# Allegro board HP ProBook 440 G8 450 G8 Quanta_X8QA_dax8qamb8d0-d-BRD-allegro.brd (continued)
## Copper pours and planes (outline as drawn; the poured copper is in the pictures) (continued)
FBVDDQ_MEM on BOTTOM (solid shape): 43.55,67.37 43.63,67.34 43.66,67.28 43.73,67.11 43.88,67.03 43.9,67.02 44.04,66.88 44.04,66.86 44.15,66.66 44.36,66.58 44.43,66.55 44.44,66.44 44.4,66.43 44.37,66.43 44.13,66.33 44.03,66.1 44.04,66.09 44.01,66.01 43.94,65.98 43.74,65.9 43.66,65.7 43.72,65.53 43.87,65.43 43.88,65.43 44.04,65.27 44.04,65.25 44.15,65.05 44.36,64.97 44.43,64.94 44.46,64.88 44.46,64.86 44.44,64.81 44.39,64.8 44.33,64.82 44.26,64.83 44.11,64.79 44,64.69 43.91,64.65 43.83,64.7 43.71,64.81 43.55,64.85 43.53,64.84 43.45,64.87 43.42,64.93 43.33,65.11 43.14,65.18 43.12,65.18 43.08,65.2 43.07,65.24 43.07,65.27 43.24,65.44 43.25,65.44 43.37,65.54 43.42,65.7 43.35,65.88 43.18,65.98 43.12,66.01 43.1,66.08 43.1,66.12 43.12,66.19 43.18,66.22 43.42,66.5 43.18,66.78 43.12,66.81 43.1,66.88 43.1,66.92 43.12,66.99 43.18,67.02 43.35,67.12 43.42,67.3 43.42,67.33 43.43,67.34 43.46,67.37 43.48,67.37
FBVDDQ_MEM on BOTTOM (solid shape): outline of 417 points within 31.44,88.77 53.77,99.62
FBVDDQ_MEM on BOTTOM (solid shape): outline of 4834 points within 31.57,59.64 49.17,88.01
FBVDDQ_MEM on IN1 (solid shape): outline of 1805 points within 31.39,63.85 46.35,76.87
FBVDDQ_MEM on IN1 (solid shape): outline of 1967 points within 31.39,81.5 46.2,93.46
FBVDDQ_MEM on IN3 (solid shape): outline of 1001 points within 33.68,64.23 37.18,76.83
FBVDDQ_MEM on IN3 (solid shape): outline of 1517 points within 36.8,70.25 52.44,85.14
GPU_BST1 on BOTTOM (solid shape): 78.59,107.34 78.51,107.26 78.51,105.51 78.23,105.23 77.87,105.23 77.75,105.36 77.75,107.54 77.76,107.56 78.59,107.56
GPU_BST2 on BOTTOM (solid shape): 56.87,105.41 56.87,104.72 56.79,104.65 56.75,104.6 56.11,103.96 56.11,103.3 56.06,103.25 55.47,103.25 55.42,103.3 55.42,104.06 56.21,104.85 56.21,105.38 56.31,105.48 56.79,105.48
GPU_PWM2 on BOTTOM (solid shape): 52.27,106.07 52.27,105 53.19,104.09 53.19,103.27 53.16,103.25 52.55,103.25 52.45,103.35 52.45,103.51 52.46,103.55 52.46,103.58 52.35,103.84 52.09,103.95 52.03,103.94 51.79,104.19 51.79,106.09 51.86,106.17 52.17,106.17
GPU_SW1 on BOTTOM (solid shape): 76.81,108.4 76.81,106.86 76.55,106.6 76.12,106.6 75.92,106.4 75.92,105.13 76.2,104.85 78.36,104.85 78.53,104.67 78.53,102.49 78.18,102.13 73.91,102.13 73.66,102.39 73.66,104.72 74.01,105.08 74.01,106.14 74.24,106.37 74.24,108.48 76.73,108.48
GPU_SW2 on BOTTOM (solid shape): 63.32,105.33 63.32,102.41 63.19,102.28 62.02,102.28 59.51,99.77 54.58,99.77 54.53,99.82 54.53,102.21 54.58,102.26 57.63,102.26 58.06,102.69 58.06,104.19 57.91,104.34 57.9,104.36 57.77,104.56 57.55,104.63 57.45,104.62 57.35,104.57 57.32,104.55 57.22,104.65 57.22,105.31 57.31,105.4 63.26,105.4
ISL95860_VDD on BOTTOM (solid shape): 82.95,108.45 82.95,107.77 82.66,107.48 81.41,107.48 81.31,107.58 81.31,108.23 81.77,108.69 82.71,108.69
ISL95860_VIN on BOTTOM (solid shape): 83.92,111.2 83.92,110.36 83.83,110.27 82.91,110.27 82.72,110.08 82.72,110.02 82.7,109.94 82.69,109.88 82.7,109.82 82.72,109.76 82.72,109.69 83.06,109.35 83.06,109.01 82.9,108.86 82.22,108.86 82.04,109.04 82.04,109.24 82.14,109.34 82.14,109.4 82.15,109.41 82.24,109.5 82.24,109.84 82.07,110.01 81.8,110.01 81.71,110.1 81.71,110.92 81.96,111.17 82.57,111.17 82.73,111.33 83.79,111.33
L_SPK+ on TOP (solid shape): 136.01,101.12 136.01,100.62 136.22,100.42 136.35,100.42 136.6,100.17 136.6,99.95 136.47,99.82 135.62,99.82 135.46,99.98 135.46,101.11 135.53,101.18 135.95,101.18
L_SPK+ on TOP (solid shape): 196.01,43.3 196.01,42.81 195.9,42.61 195.87,42.39 195.87,42.35 195.48,41.96 195.48,41.19 195.43,41.14 195.29,41.14 195.23,41.19 195.23,42.19 195.24,42.2 195.35,42.27 195.42,42.38 195.48,42.43 195.48,42.56 195.48,43.17 195.48,43.28 195.46,43.31 195.48,43.35 195.54,43.42 195.89,43.42
L_SPK+ on BOTTOM (solid shape): 137.35,102.54 137.35,100.62 137.34,100.6 137.26,100.51 136.98,100.51 136.72,100.26 136.72,99.97 136.49,99.74 136.1,99.74 135.42,100.42 135.42,101.71 135.81,102.11 135.81,102.46 135.94,102.58 137.31,102.58
L_SPK+ on IN3 (solid shape): 136.73,100.85 136.73,100.06 136.55,99.89 135.96,99.89 135.48,100.37 135.48,100.9 135.94,101.36 136.22,101.36
L_SPK+ on IN3 (solid shape): 197,44.52 197,44.42 197.05,44.42 197.18,44.3 197.18,43.76 196.47,43.05 196.47,42.95 195.81,42.29 195.65,42.29 195.48,42.47 195.48,43.46 196.7,44.68 196.85,44.68
L_SPK- on TOP (solid shape): 138.71,101.14 138.71,100.01 138.55,99.85 137.68,99.85 137.54,99.99 137.54,100.34 138,100.8 138,101.09 138.12,101.22 138.63,101.22
L_SPK- on TOP (solid shape): 195.37,43.24 195.37,43.17 195.37,42.57 195.37,42.48 195.12,42.22 195.12,41.31 195.01,41.2 194.89,41.2 194.8,41.28 194.8,42.42 194.81,42.47 194.81,42.59 194.8,42.65 194.8,43.04 194.81,43.09 194.82,43.14 194.82,43.23 194.83,43.25 194.95,43.37 195.24,43.37
L_SPK- on BOTTOM (solid shape): 138.69,102.54 138.69,100.05 138.54,99.9 137.73,99.9 137.6,100.02 137.6,100.49 137.61,100.5 137.61,102.54 137.71,102.64 138.59,102.64
L_SPK- on IN3 (solid shape): 138.68,101.16 138.68,100.04 138.51,99.87 137.66,99.87 137.56,99.96 137.56,101.26 137.87,101.56 138.28,101.56
L_SPK- on IN3 (solid shape): 195.86,44.68 195.86,44.14 195.35,43.63 195.35,42.39 195.25,42.29 194.97,42.29 194.84,42.42 194.84,43.86 194.94,43.97 194.94,44.47 195.29,44.82 195.72,44.82
LCD_P on TOP (solid shape): outline of 170 points within 24.03,35.08 32.94,38.12
LCD_P on BOTTOM (solid shape): 33.63,35.06 33.63,33.47 33.07,32.92 32.04,32.92 31.75,33.21 31.75,35.53 31.82,35.61 33.08,35.61
MP2941_SW1 on BOTTOM (solid shape): 115.78,106.64 115.78,105.87 115.76,105.87 115.76,105.08 115.78,105.08 115.78,104.58 116.08,104.28 116.08,103.14 116.58,102.64 117.79,102.64 117.95,102.48 117.95,102.09 116.81,100.95 116.81,100.91 116.81,100.9 116.78,100.83 116.77,100.74 116.78,100.66 116.81,100.59 116.81,100.57 116.81,100.27 116.81,100.26 116.78,100.18 116.77,100.1 116.78,100.01 116.81,99.94 116.81,99.93 116.81,99.61 116.81,99.6 116.78,99.52 116.77,99.44 116.78,99.35 116.81,99.28 116.81,99.27 116.81,97.91 116.61,97.71 112.67,97.71 112.59,97.8 112.59,101.23 113.24,101.89 113.24,103.11 113.78,103.64 113.78,104.13 113.94,104.29 114.41,104.29 114.53,104.41 114.53,106.7 114.61,106.78 115.64,106.78
MP2941_VCC on BOTTOM (solid shape): 112.16,109.55 112.16,108.61 112.72,108.05 112.72,107.7 112.83,107.59 112.84,107.58 113.61,107.58 113.63,107.56 113.64,107.54 113.64,107.52 113.64,107.44 113.64,107.42 113.63,107.4 113.61,107.38 112.84,107.38 112.84,107.38 111.7,107.38 111.45,107.63 111.45,108.02 111,108.47 111,109.42 111.2,109.62 112.09,109.62
NB680ABST on BOTTOM (solid shape): 144.25,15.55 144.25,15.36 144.84,14.77 144.84,13.36 144.82,13.33 144.56,13.19 144.46,12.94 144.53,12.73 144.71,12.59 144.78,12.52 144.75,12.43 144.71,12.38 143.7,12.38 143.51,12.57 143.51,13.42 143.63,13.54 143.64,13.55 143.81,13.68 143.88,13.89 143.86,14.01 143.8,14.11 143.8,14.69 143.8,14.7 143.8,14.74 142.99,15.55 142.99,15.7 143.04,15.75 144.05,15.75
NB680ABST_S on BOTTOM (solid shape): 144.85,11.91 145.62,11.91 145.74,11.78 145.74,11.15 145.62,11.02 143.71,11.02 143.53,11.2 143.53,11.96 143.63,12.06 144.7,12.06
NB680ABSW on TOP (solid shape): 145.02,16.29 145.02,14.79 144.83,14.61 144.82,14.6 144.8,14.59 144,14.59 143.84,14.76 143.84,15.64 144.07,15.87 144.07,15.91 144.57,16.41 144.9,16.41
NB680ABSW on BOTTOM (solid shape): 148.61,16.76 148.61,13.1 147.55,12.04 146.24,12.04 146.19,12.05 146.15,12.05 146.11,12.05 146.06,12.04 145.51,12.04 145.29,12.26 145.29,14.87 144.21,15.94 144.21,15.94 144.15,16 142.25,16 142.17,16.08 142.17,16.28 142.27,16.37 144.36,16.37 144.99,17 148.37,17
NB691_BS on BOTTOM (solid shape): 124.1,14.93 124.1,14.27 124.36,14.02 124.89,14.02 124.99,13.92 124.99,13.31 124.92,13.23 123.59,13.23 123.24,13.59 123.24,14.96 123.11,15.09 122.76,15.09 122.68,15.16 122.68,15.44 123.44,15.44 123.44,15.47 123.57,15.47
NB691_BST on BOTTOM (solid shape): 125.96,12.88 125.96,12.06 125.8,11.91 124.2,11.91 124.1,12.01 124.1,12.95 124.18,13.03 125.8,13.03
NB691_LX on TOP (solid shape): 127.56,14.78 127.56,13.41 127.38,13.23 126.95,13.23 126.12,14.06 125.36,14.06 125.27,14.15 125.27,14.68 125.47,14.88 127.46,14.88
NB691_LX on BOTTOM (solid shape): 127.53,16.63 127.53,13.46 126.85,12.77 126.85,12.7 126.78,12.64 126.77,12.63 126.66,12.52 126.34,12.52 126.21,12.65 126.21,13.21 126.08,13.33 125.32,13.33 125.19,13.46 125.19,14.09 125.02,14.27 124.51,14.27 124.33,14.45 124.33,14.97 123.59,15.71 121.9,15.71 121.87,15.75 121.87,15.88 121.93,15.95 123.38,15.95 123.92,16.49 124.47,16.49 124.94,16.96 127.2,16.96
NPCE576H_AGND on BOTTOM (solid shape): 193.29,14.67 193.33,14.62 193.92,14.62 193.98,14.56 193.98,13.75 193.96,13.68 193.95,13.62 193.99,13.47 194.09,13.36 194.13,13.33 194.17,13.31 194.2,13.31 194.2,13.31 194.31,13.31 194.47,13.15 194.47,13.15 194.58,13.05 194.73,13.02 194.77,13.02 194.82,13.03 194.91,13.03 194.97,13.06 195.02,13.1 195.56,13.1 195.61,13.08 195.87,13.08 195.94,13.12 195.97,13.12 196.11,12.98 196.11,12.89 196.08,12.83 196.08,12.7 196.06,12.69 195.56,12.69 195.25,12.38 193.62,12.38 193.55,12.46 193.55,13.13 193.43,13.24 193.43,13.58 193.29,13.73 192.89,13.73 192.25,14.37 192.25,14.74 192.33,14.82 193.29,14.82
NVVDD on TOP (solid shape): outline of 938 points within 62.78,71.47 75.96,81.96
NVVDD on BOTTOM (solid shape): outline of 117 points within 59.51,94.18 77.75,101.28
NVVDD on BOTTOM (solid shape): outline of 2071 points within 62.93,72.25 79.32,83.34
NVVDD on IN1 (solid shape): outline of 2868 points within 61.59,72.25 80.91,102.61
NVVDD on SVCC (solid shape): 80.22,101.76 80.19,101.68 80.18,101.6 80.28,101.34 80.54,101.23 80.63,101.24 80.71,101.27 80.72,101.26 80.72,99.44 80.57,99.31 80.51,99.11 80.57,98.92 80.72,98.79 80.72,87.3 78.76,85.34 78.71,85.26 78.69,85.16 78.69,82.88 78.71,82.78 78.76,82.7 79.45,82.01 79.45,77.9 76.04,74.5 75,74.5 74.91,74.48 74.82,74.42 73.76,73.35 73.05,73.35 72.93,73.45 72.77,73.49 72.51,73.38 72.41,73.12 72.41,73.09 72.41,73.05 72.34,73.07 72.26,73.08 72,72.97 71.9,72.72 71.9,72.65 71.92,72.59 63.55,72.59 63.45,72.7 63.45,76.81 63.56,76.94 63.61,77.11 63.56,77.28 63.45,77.41 63.45,81.38 64.06,81.99 69.04,81.99 69.13,82.01 69.22,82.06 72.14,84.98 72.19,85.07 72.21,85.16 72.21,89.71 72.25,89.79 72.26,89.89 72.25,89.99 72.21,90.08 72.21,91.73 72.46,91.84 72.56,92.09 72.46,92.34 72.21,92.45 72.21,93.8 72.19,93.9 72.14,93.98 67.94,98.17 67.86,98.23 67.77,98.25 61.95,98.25 61.93,98.27 61.54,98.66 61.54,101.75 62.38,102.59 79.39,102.59
NVVDD on IN2 (solid shape): outline of 1516 points within 63.07,72.47 79.88,82.52
PEX_LX on BOTTOM (solid shape): 67.08,59.69 67.08,58.82 67.03,58.77 65.56,58.77 65.14,58.36 65.14,56.8 65.06,56.72 64.07,56.72 64.06,56.72 63.78,56.72 63.7,56.79 63.7,58.9 64.39,59.59 64.54,59.67 64.64,59.81 66.95,59.81
PEX_VDD on TOP (solid shape): 65.61,59.21 65.61,57.81 65.45,57.66 60.86,57.66 60.72,57.79 60.72,60.26 60.86,60.4 64.41,60.4
PEX_VDD on BOTTOM (solid shape): outline of 97 points within 53.52,57.43 61.44,71.75
PEX_VDD on IN1 (solid shape): outline of 1046 points within 55.98,57.1 67.1,72.49
PEX_VDD on IN2 (solid shape): 64.65,60.03 64.65,59.42 62.33,57.1 56.82,57.1 56.54,57.38 56.54,57.71 59.13,60.29 64.39,60.29
PEXVDD_EN1 on BOTTOM (solid shape): outline of 123 points within 82.09,83.26 85.29,85.9
PVADPTR on TOP (solid shape): 177.04,86.26 177.04,86.1 177.01,86.03 177,85.95 177.01,85.87 176.48,85.34 175.66,85.34 175.21,85.8 174.69,85.8 174.57,85.93 174.57,86.3 174.62,86.36 175.71,86.36 175.78,86.33 175.91,86 176.17,85.89 176.43,86 176.54,86.25 176.53,86.29 176.56,86.37 176.64,86.4 176.89,86.4
PVADPTR on BOTTOM (solid shape): outline of 145 points within 173.71,83.51 179.78,90.24
R_SPK+ on TOP (solid shape): 142.15,101.12 142.15,100.33 142.11,100.28 142.08,100.23 142.08,100.04 141.91,99.86 141.09,99.86 140.97,99.99 140.97,101.06 141.09,101.19 142.07,101.19
R_SPK+ on TOP (solid shape): 194.06,43.25 194.06,42.12 194.29,41.89 194.29,41.17 194.23,41.12 194.06,41.12 194.05,41.14 193.99,41.14 193.93,41.2 193.93,41.79 193.61,42.11 193.61,43.34 193.68,43.41 193.9,43.41
R_SPK+ on BOTTOM (solid shape): 142.03,102.42 142.03,100.1 141.85,99.92 141,99.92 140.87,100.05 140.87,100.42 140.78,100.51 140.41,100.51 140.35,100.57 140.35,102.56 140.43,102.64 141.81,102.64
R_SPK+ on IN3 (solid shape): 193.67,44.09 193.67,43.74 194.08,43.33 194.08,42.44 193.9,42.26 193.42,42.26 192.91,42.77 192.91,44.09 193.06,44.24 193.52,44.24
R_SPK+ on IN3 (solid shape): 142.31,100.65 142.31,100.41 142.14,100.3 142.07,100.1 142.1,99.97 142.17,99.87 142.09,99.78 141.09,99.78 140.92,99.96 140.92,100.65 141.45,101.18 141.78,101.18
R_SPK- on TOP (solid shape): 194.7,43.27 194.7,41.28 194.59,41.17 194.49,41.17 194.4,41.25 194.4,41.98 194.36,42.02 194.36,42.03 194.21,42.18 194.21,43.26 194.29,43.35 194.62,43.35
R_SPK- on TOP (solid shape): 140.06,101.06 140.06,100.65 140.1,100.61 140.1,100.19 140.1,100.15 140.1,100.11 140.1,100.08 140.1,99.99 139.99,99.87 139.08,99.87 139,99.95 139,101.04 139.13,101.17 139.96,101.17
R_SPK- on BOTTOM (solid shape): 140.08,102.47 140.08,100.02 139.96,99.9 139.1,99.9 138.94,100.05 138.94,102.44 139.14,102.64 139.91,102.64
R_SPK- on IN3 (solid shape): 140.08,101.05 140.08,99.91 139.98,99.81 139.75,99.81 139.69,99.87 139.33,99.87 139.25,99.95 139.13,99.95 138.99,100.1 138.99,100.98 139.16,101.16 139.98,101.16
R_SPK- on IN3 (solid shape): 194.69,44.8 194.69,43.89 194.71,43.86 194.71,42.47 194.56,42.31 194.33,42.31 194.21,42.44 194.21,43.56 193.93,43.84 193.93,44.83 194.03,44.93 194.56,44.93
SM_VREF on TOP (solid shape): 154.38,22.96 154.38,21.44 154,21.05 154,20.6 153.77,20.37 153.11,20.37 153.01,20.47 153.01,21.64 153.34,21.97 153.34,22.78 153.67,23.11 154.23,23.11
SMDDR_VREF_DQ1_M1 on TOP (solid shape): 111.73,24.66 111.73,24.23 111.94,24.03 113.05,24.03 113.18,23.9 113.18,23.16 112.98,22.96 112.22,22.96 111.99,22.73 111.99,20.85 111.76,20.62 110.87,20.62 110.81,20.69 110.81,21.98 111.05,22.22 111.05,23.92 110.89,24.08 110.89,24.69 110.97,24.76 111.63,24.76
SMDDR_VREF_DQ1_M3 on TOP (solid shape): 114.12,22.32 114.12,21.59 114.02,21.49 113.56,21.49 113.33,21.26 113.33,20.67 113.23,20.57 112.39,20.57 112.22,20.75 112.22,22.43 112.44,22.65 113.79,22.65
SN3V on TOP (solid shape): 145.86,15.63 145.86,13.5 145.69,13.33 145.14,13.33 145.01,13.46 145.01,13.83 145.13,13.95 145.13,15.62 145.21,15.69 145.79,15.69
SN_VCCIN2 on TOP (solid shape): 104.62,103.53 104.62,101.83 104.47,101.67 103.91,101.67 103.63,101.95 103.63,102.89 103.12,103.4 103.12,103.55 103.25,103.68 104.47,103.68
SY127F_LX on BOTTOM (solid shape): 170.43,17.42 170.43,17.24 171.32,16.36 172.34,16.36 172.46,16.23 172.46,12.88 172.29,12.7 170.48,12.7 170.13,13.05 170.13,13.38 169.85,13.66 165.4,13.66 165.3,13.76 165.3,14.17 165.45,14.32 169.95,14.32 170.13,14.5 170.13,16.46 169.72,16.86 169.72,17.42 169.85,17.55 169.9,17.55 170.01,17.65 170.2,17.65
TYPEC1_USB0 on BOTTOM (solid shape): 170.25,104.59 170.25,104.26 170.03,104.04 169.9,104.04 169.8,103.93 169.8,103.84 169.78,103.8 169.77,103.77 169.77,103.4 169.7,103.32 169.39,103.32 169.24,103.48 169.24,103.68 169.06,103.85 169.06,104.35 169.39,104.67 170.18,104.67
TYPEC1_USB0 on BOTTOM (solid shape): 181.27,88.51 181.97,88.51 182.31,88.17 182.31,87.89 182.3,87.87 182.3,87.35 182.8,86.84 182.83,86.84 183.11,86.56 183.61,86.56 183.82,86.36 183.82,84.8 183.73,84.72 182.63,84.72 182.45,84.53 181.56,84.53 181.25,84.22 180.45,84.22 180.37,84.31 180.31,84.47 180.19,84.59 180.19,86.76 180.58,87.16 180.58,88.5 180.67,88.59 181.18,88.59
TYPEC_VBUS on BOTTOM (solid shape): 204.58,103.57 204.58,101.82 204.57,101.82 204.57,101.19 204.29,100.91 202.31,100.91 202.16,101.06 202.16,103.03 202.5,103.86 202.68,104.04 203.1,104.21 203.93,104.21
TYPEC_VBUS on BOTTOM (solid shape): 211.75,107.65 211.81,107.65 211.83,107.62 211.92,107.62 211.96,107.6 212.16,107.6 212.29,107.47 212.29,107.26 212.16,107.13 210.82,107.13 210.36,106.68 209.9,106.68 209.83,106.75 209.83,107.03 210.13,107.34 210.13,107.57 210.34,107.77 210.44,107.77 210.54,107.87 211.52,107.87
TYPEC_VBUS on BOTTOM (solid shape): 189.91,89.05 189.91,87.95 189.84,87.88 189.71,87.88 189.71,88.89 189.51,88.89 189.51,87.88 189.31,87.88 189.31,88.89 189.11,88.89 189.11,87.88 188.8,87.88 188.64,87.73 188.64,87.45 188.58,87.39 187.61,87.39 187.56,87.44 187.56,87.45 187.49,87.56 187.38,87.63 187.12,87.63 187.1,87.63 186.95,87.63 186.84,87.55 186.77,87.45 186.77,87.3 186.71,87.25 186.71,84.83 186.61,84.73 185.93,84.73 185.82,84.63 185.47,84.63 185.21,84.38 184.86,84.38 184.41,84.83 184.41,88.37 184.11,88.67 184.11,88.96 184.38,89.23 185.72,89.23 185.93,89.43 189.53,89.43
TYPEC_VBUS on SVCC (solid shape): outline of 394 points within 180.67,87.32 196.29,105.17
TYPEC_VBUS on IN2 (solid shape): outline of 1202 points within 192.57,99.15 212.95,111.6
VADPBL on BOTTOM (solid shape): outline of 396 points within 147.21,84.55 174.88,100.28
N17777419 on BOTTOM (solid shape): 198.88,12.48 198.98,12.47 199.02,12.43 199.02,11.6 198.92,11.5 197.05,11.5 196.92,11.63 196.92,12.29 197.02,12.38 197.24,12.38 197.32,12.43 197.38,12.49 198.83,12.49
N25319276 on TOP (solid shape): 153.46,99.97 153.46,98.24 152.88,97.66 152.05,97.66 151.95,97.76 151.95,98.09 152.08,98.22 152.32,98.22 152.58,98.47 152.58,98.51 152.59,98.53 152.59,98.93 152.58,98.94 152.58,98.98 152.42,99.13 152.24,99.13 152.09,99.29 152.09,99.78 152.01,99.86 152.01,99.86 151.78,100.1 150.29,100.1 149.99,99.79 149.3,99.79 149.22,99.87 149.22,100.53 149.29,100.59 152.84,100.59
N27367629 on TOP (solid shape): 91,77.28 91.77,77.28 91.82,77.25 91.86,77.24 92.15,77.24 92.23,77.16 92.23,76.96 92.1,76.83 92.1,76.51 92,76.41 91.37,76.41 91.19,76.23 91.19,75.92 91.13,75.87 90.37,75.87 89.71,76.53 89.71,77.01 90.08,77.01 90.08,76.96 90.09,76.9 90.11,76.85 90.14,76.81 90.17,76.76 90.21,76.73 90.25,76.7 90.3,76.67 90.35,76.65 90.41,76.64 90.46,76.64 90.51,76.65 90.57,76.66 90.62,76.68 90.66,76.71 90.7,76.74 90.74,76.78 90.77,76.83 90.79,76.88 90.81,76.93 90.82,76.98 90.82,77.04 90.81,77.09 90.79,77.14 90.77,77.19 90.74,77.24 90.7,77.28 90.66,77.31 90.62,77.34 90.57,77.36 90.51,77.37 90.46,77.38 90.41,77.38 90.35,77.37 90.3,77.35 90.25,77.33 90.21,77.29 90.17,77.26 90.14,77.21 90.11,77.17 90.09,77.12 90.08,77.06 90.08,77.01 89.71,77.01 89.71,77.42 89.89,77.59 90.68,77.59
N27367663 on TOP (solid shape): 86.51,73.15 87.53,73.15 87.58,73.1 87.58,72.47 87.5,72.35 87.47,72.21 87.49,72.08 87.56,71.96 87.58,71.95 87.58,71.91 87.73,71.75 87.73,71.45 87.64,71.35 87.35,71.35 87.24,71.24 86.41,71.24 86.05,70.89 85.06,70.89 85.01,70.94 85.01,72.11 85.21,72.31 85.21,73.28 85.29,73.35 86.31,73.35
N27367840 on TOP (solid shape): 90.35,75.54 90.35,75.11 90.17,74.93 90.12,74.94 89.88,74.84 89.76,74.62 89.75,74.57 88.83,74.57 88.8,74.6 88.8,75.15 88.67,75.28 87.73,75.28 87.6,75.41 87.6,75.87 87.48,75.99 87.48,76.4 87.6,76.53 88.52,76.53 88.69,76.71 89.18,76.71
N27367840 on TOP (solid shape): 89.97,72.97 89.97,72.61 90.03,72.55 90.08,72.48 90.15,72.43 90.16,72.42 90.16,72.12 90.88,71.4 90.88,70.56 90.8,70.48 89.05,70.48 88.97,70.56 88.97,70.69 87.9,71.76 87.9,71.77 87.82,71.9 87.7,71.98 87.63,72.06 87.63,72.34 87.73,72.44 88.69,72.44 88.78,72.52 88.78,73.11 88.81,73.15 89.79,73.15
N27367840 on BOTTOM (solid shape): outline of 120 points within 86.79,71.33 89.69,77.04
N27367864 on TOP (solid shape): 86.38,77.75 86.38,77.45 86.52,77.31 86.59,77.28 86.6,77.28 86.69,77.19 87.12,77.19 87.32,76.99 87.32,75.92 87.45,75.79 87.45,75.31 87.53,75.22 87.53,74.61 87.5,74.57 86.62,74.57 86.22,74.97 86.24,75.04 86.24,75.08 86.13,75.34 85.88,75.44 85.77,75.43 85.68,75.39 85.64,75.36 85.61,75.4 85.41,75.4 85.11,75.69 85.11,77.25 85.12,77.29 85.12,77.93 85.32,78.13 86,78.13
N27368325 on BOTTOM (solid shape): 55.88,57.27 57.63,57.27 57.76,57.15 57.76,56.18 57.76,56.18 57.76,55.7 57.75,55.69 53.93,55.69 53.21,56.41 53.21,56.97 53.21,56.99 53.23,57.01 53.31,57.09 54.56,57.09 54.56,57.1 54.68,57.1 54.78,57 54.8,56.98 54.81,56.97 54.95,56.81 55.15,56.75 55.41,56.86 55.51,57.12 55.51,57.16 55.5,57.21 55.51,57.23 55.56,57.28 55.88,57.28
N36756780 on TOP (solid shape): 117.19,16.15 117.19,13.51 117.17,13.48 116.46,13.48 116.36,13.59 116.36,14.36 116.06,14.65 116.06,16.02 116.08,16.09 116.08,16.15 116.08,16.19 116.08,16.23 116.15,16.3 117.04,16.3
N37096732 on BOTTOM (solid shape): 174.62,85.98 174.62,84.96 173.07,83.41 172.13,83.41 172.08,83.46 172.08,84.02 172.13,84.07 172.13,84.66 172.18,84.71 173.02,84.71 173.91,85.6 173.91,85.98 173.99,86.05 174.55,86.05
N38936280 on TOP (solid shape): 66.06,12.37 66.06,10.56 65.94,10.44 63.02,10.44 62.74,10.72 62.74,13.74 63.24,14.25 64.18,14.25
N39257899 on TOP (solid shape): 196.57,42.34 196.57,42.19 195.96,41.58 195.93,41.58 195.83,41.48 195.83,41.2 195.78,41.15 195.63,41.15 195.58,41.2 195.58,41.88 195.91,42.22 195.98,42.27 196.04,42.34 196.19,42.49 196.42,42.49
N39257899 on TOP (solid shape): 193.42,43.91 193.42,42.11 193.81,41.72 193.81,41.46 193.7,41.35 192.81,41.35 191.79,42.36 191.79,43.36 191.76,43.39 191.76,43.76 191.77,43.81 191.77,43.85 191.77,43.89 191.76,43.98 191.82,44.04 193.29,44.04
N39257899 on BOTTOM (solid shape): 196.54,42.36 196.54,42.14 195.81,41.4 195.81,40.71 195.68,40.59 192.05,40.59 192.01,40.62 192.01,41.12 192.15,41.26 192.29,41.26 192.62,41.59 192.62,41.89 193.02,42.29 193.55,42.29 193.67,42.19 193.83,42.16 193.97,42.19 194.09,42.27 194.1,42.29 194.18,42.29 194.2,42.27 194.46,42.16 194.72,42.27 194.74,42.29 194.82,42.29 194.83,42.27 195.1,42.16 195.36,42.27 195.37,42.29 195.45,42.29 195.47,42.27 195.59,42.19 195.73,42.16 195.91,42.21 196.04,42.33 196.2,42.49 196.42,42.49
N46796009 on TOP (solid shape): 128.42,14.86 128.42,13.41 128.52,13.31 128.52,13.03 128.43,12.94 127.97,12.94 127.71,13.2 127.71,14.86 127.75,14.91 128.37,14.91
N47664126 on BOTTOM (solid shape): 149.25,11.31 150.16,11.31 150.36,11.11 150.36,9.64 150.24,9.52 149.32,9.52 149.2,9.64 149.2,10.37 148.76,10.81 148.76,10.81 148.64,10.93 148.64,11.35 148.77,11.48 149.08,11.48
N47664563 on BOTTOM (solid shape): 31.82,8.89 31.82,6.4 31.32,5.89 30.44,5.89 30.44,6.64 30.44,6.8 30.24,6.8 30.24,5.89 30.05,5.89 29.94,6 29.94,6.64 29.94,6.8 29.92,6.8 29.92,7.39 29.95,7.41 30.12,7.54 30.18,7.74 30.21,7.81 30.52,7.95 30.61,8.2 30.55,8.41 30.37,8.55 30.3,8.62 30.33,8.71 30.6,8.99 31.72,8.99
N48061147 on BOTTOM (solid shape): 127.72,104.02 128.33,104.02 128.39,104.08 128.75,104.08 128.82,104 128.83,103.98 128.83,103.72 128.67,103.56 128.67,103.11 128.62,103.06 126.65,103.06 126.59,103.12 126.59,104.09 126.65,104.15 127.59,104.15
N48061149 on BOTTOM (solid shape): 126.09,104.4 126.03,104.34 124.97,104.34 124.24,103.62 124.24,103.05 124.19,102.99 123.06,102.99 122.94,103.11 122.94,104.12 123.74,104.93 126.09,104.93
N48125412 on BOTTOM (solid shape): 155.4,101.67 156.41,101.67 156.54,101.55 156.54,100.28 156.41,100.15 154.63,100.15 154.51,100.28 154.51,100.53 154.63,100.66 154.89,100.66 154.99,100.76 155.04,100.8 155.08,100.85 155.14,100.91 155.14,101.24 154.81,101.57 154.81,101.75 154.91,101.85 155.22,101.85
N50419052 on TOP (solid shape): 134.36,94.16 134.36,93.62 134.5,93.49 134.52,93.46 134.55,93.43 134.64,93.34 135.05,93.34 135.26,93.13 135.75,93.13 135.84,93.04 135.84,92.25 134.97,91.39 133.68,91.39 133.6,91.46 133.6,91.84 132.74,92.71 132.74,93.09 133.3,93.65 133.3,94.21 133.35,94.26 134.26,94.26
N50419064 on TOP (solid shape): 135.33,99.54 136.42,99.54 136.88,99.08 136.88,98.12 136.84,98.04 136.81,97.96 136.81,97.95 136.68,97.81 136.68,96.77 136.62,96.71 135.82,96.71 135.76,96.77 135.76,97.19 135.77,97.19 135.76,97.21 135.76,97.27 135.71,97.32 135.71,97.79 135.75,97.89 135.77,97.99 135.76,98.08 135.73,98.16 135.78,98.26 135.79,98.37 135.69,98.63 135.43,98.74 135.3,98.71 135.19,98.64 135.12,98.61 135.05,98.64 134.94,98.71 134.8,98.74 134.55,98.63 134.44,98.37 134.44,98.35 134.28,98.19 134.28,98.19 134.21,98.12 134.21,98.07 134.2,98.05 134.18,98.02 134.18,97.99 134.18,97.96 133.94,97.72 133.94,97.12 134.01,97.04 134.01,96.41 134.06,96.36 134.06,95.72 134.04,95.68 134.01,95.67 133.37,95.67 133.37,97.79 133.12,98.04 133.12,99.03 133.81,99.72 135.15,99.72
N50522975 on BOTTOM (solid shape): 55.83,96.04 55.83,95.4 55.55,95.12 55.55,93.95 55.5,93.9 54.81,93.9 54.76,93.95 54.76,95.12 54.99,95.35 54.99,96.04 55.07,96.11 55.75,96.11
N50522977 on BOTTOM (solid shape): 59,95.43 59,93.6 58.37,92.96 56.77,92.96 56.67,93.06 56.67,93.67 56.74,93.75 57.53,93.75 57.81,94.03 57.81,95.48 57.86,95.53 58.9,95.53
N51044000 on BOTTOM (solid shape): 200.15,75.77 200.15,74.09 200.08,74.02 199.42,74.02 199.35,74.09 199.35,74.33 197.43,76.25 197.43,77.73 197.49,77.8 198.12,77.8
N51044000 on IN3 (solid shape): outline of 206 points within 185.24,80.46 187.65,84.4
N51454542 on TOP (solid shape): 30.25,82.82 31.12,82.82 31.13,82.81 31.35,82.81 31.54,82.62 31.54,80.57 31.41,80.43 29.88,80.43 29.39,79.94 29.39,78.63 29.24,78.48 24.92,78.48 24.76,78.64 24.76,80.46 24.71,80.52 24.71,81.8 24.56,81.96 23.86,81.96 23.77,82.04 23.77,83.13 23.82,83.18 29.89,83.18
N51454542 on BOTTOM (solid shape): 29.74,80.59 29.74,77.34 29.59,77.19 25.86,77.19 25.25,77.8 25.25,81.54 25.68,81.97 28.36,81.97
N52915353 on BOTTOM (solid shape): 32.99,84.02 32.99,83.36 32.61,82.98 32.61,82.65 32.51,82.55 31.62,82.55 31.47,82.7 31.47,84 31.54,84.07 32.43,84.07 32.51,84.15 32.87,84.15
N53077023 on TOP (solid shape): 27.82,63.14 27.82,61.65 27.31,61.15 24.46,61.15 24.15,61.47 24.15,62.51 24.15,62.51 24.18,62.53 26.06,62.53 26.77,63.24 27.71,63.24
N54154109 on TOP (solid shape): 75.31,80.49 75.31,79.04 75.13,78.86 75.13,78.48 74.9,78.26 74.01,78.26 73.84,78.43 73.84,78.76 73.68,78.92 73.25,78.92 73.15,79.02 73.15,79.39 73.15,79.41 73.17,79.43 73.21,79.48 73.44,79.7 74.06,79.7 74.24,79.88 74.24,80.52 74.34,80.62 75.18,80.62
N54154109 on IN3 (solid shape): outline of 220 points within 69.41,78.28 75.12,83.9
N54169728 on TOP (solid shape): outline of 119 points within 71.3,74.78 83.36,84.3
N54177392 on TOP (solid shape): outline of 123 points within 59.76,85.77 61.31,88.06
N69862027 on TOP (solid shape): 138.96,79.02 139.16,79.02 139.29,78.89 139.29,78.61 139.16,78.48 138.63,78.48 138.6,78.52 138.2,78.52 138.2,78.58 138.21,78.6 138.21,78.86 138.16,78.94 138.09,79.01 138.09,79.18 138.27,79.36 138.62,79.36
N69862027 on BOTTOM (solid shape): 138.67,79.22 138.67,79.1 138.8,78.97 139.24,78.97 139.34,78.86 139.34,78.66 139.17,78.48 139.04,78.48 138.98,78.51 138.92,78.52 138.87,78.51 138.8,78.48 138.78,78.48 138.43,78.13 138.29,78.13 138.2,78.22 138.16,78.27 138.08,78.34 138.05,78.42 138.09,78.49 138.14,78.55 138.18,78.61 138.18,78.85 138.16,78.89 138.13,78.93 138.11,79 138.13,79.06 138.13,79.19 138.27,79.33 138.55,79.33

Small or netless copper shapes (teardrops, artwork), in the pictures only: 53 on TOP, 58 on BOTTOM, 55 on IN1, 1 on SVCC, 30 on IN2, 56 on IN3

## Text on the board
Ref Des/Silkscreen Bottom: FAN | BAT | KB | SPK | DC-IN | SPI ROM | RTC | TBT ROM | WLAN | EC ROM | WWAN | IO board | SSD | OLAD | SMART | LCD | TP | KBL | NATG | NFC | FR | INT SIM | Copyright 2020 HP Development Company. L.P | Please do not print out the lines with 0.39mils/0.01mm in width | DAX8QAMB8D0 REV:D | MODEL:X8QA | DDR CHB | DDR CHA
User.Comments: L | D | 18x49 | 80x100 | 114.4 | 218.04
Ref Des/Silkscreen Top: IO board | Please do not print out the lines with 0.39mils/0.01mm in width | DAX8QAMB8D0 REV:D
SGND: GND | AGND
User.12: +3V | +5V | +VIN | +3VPCU | NVVDD | +1.8V_DEEP_SUS | +VCCIN | GND | +VCCIN_AUX | +VCC1.05_OUT_FET | +3V_DEEP_SUS_PRIME | +5VPCU | TYPEC_VBUS | AGND
User.28: REV:A-7
User.32: GND | AGND
User.33: gnd | agnd | +3VPCU
User.35: GND | AGND | +5V
User.45: Excess check:Dec 25 15:32:30 2019 | No Route Under Component:Dec 25 15:39:02 2019 | PadStack_Check:Dec 25 15:15:01 2019 | XY-Check acute:Dec 25 15:33:47 2019 | XY-Create nettxt:Dec 23 13:20:36 2019 | XY-Create plane:Dec 25 15:17:03 2019 | XY-Cross plane-BOTTOM-SGND1:Dec 25 15:35:45 2019 | XY-Cross plane-IN1-SGND:Dec 25 15:34:49 2019 | XY-Cross plane-IN2-SVCC:Dec 25 15:35:01 2019 | XY-Cross plane-IN3-SGND1:Dec 25 15:35:12 2019 | XY-Cross plane-IN3-SVCC:Dec 25 15:35:26 2019 | XY-Cross plane-TOP-SGND:Dec 25 15:34:31 2019 | XY-Dxf to pin check:Dec 25 15:16:42 2019 | XY-Etch cross-IN1-IN2:Dec 25 15:34:41 2019 | XY-Etch ref-BOTTOM-SGND1:Dec 25 15:36:08 2019 | XY-Etch ref-IN1-SGND:Dec 25 15:35:01 2019 | XY-Etch ref-IN2-SVCC:Dec 25 15:35:12 2019 | XY-Etch ref-IN3-SGND1:Dec 25 15:35:26 2019 | XY-Etch ref-IN3-SVCC:Dec 25 15:35:44 2019 | XY-Etch ref-TOP-SGND:Dec 25 15:34:41 2019 | XY-Excess check:Dec 25 15:32:30 2019 | XY-NO Route Under Component:Dec 25 15:39:02 2019 | XY-Outline check:Dec 25 15:39:09 2019 | XY-PadStack_Check:Dec 25 15:15:01 2019 | XY-Plane net check:Dec 25 15:17:30 2019 | XY-Prop check:Dec 25 15:34:26 2019 | XY-TP check:Nov 10 19:42:11 2019 | XY-shape min check:Dec 25 15:11:01 2019 | XY-via check:Dec 25 15:38:00 2019 | check acute:Dec 25 15:33:47 2019 | create nettxt:Dec 23 13:20:36 2019 | create plane:Dec 25 15:17:03 2019 | cross plane-BOTTOM-SGND1:Dec 25 15:35:45 2019 | cross plane-IN1-SGND:Dec 25 15:34:49 2019 | cross plane-IN2-SVCC:Dec 25 15:35:01 2019 | cross plane-IN3-SGND1:Dec 25 15:35:12 2019 | cross plane-IN3-SVCC:Dec 25 15:35:26 2019 | cross plane-TOP-SGND:Dec 25 15:34:31 2019 | dxf to pin check:Dec 25 15:16:42 2019 | etch cross-IN1-IN2:Dec 25 15:34:41 2019 | etch ref-BOTTOM-SGND1:Dec 25 15:36:08 2019 | etch ref-IN1-SGND:Dec 25 15:35:01 2019 | etch ref-IN2-SVCC:Dec 25 15:35:12 2019 | etch ref-IN3-SGND1:Dec 25 15:35:26 2019 | etch ref-IN3-SVCC:Dec 25 15:35:44 2019 | etch ref-TOP-SGND:Dec 25 15:34:41 2019 | outline check:Dec 25 15:39:09 2019 | plane net check:Dec 25 15:17:30 2019 | prop check:Dec 25 15:34:26 2019 | shape min check:Dec 25 15:11:01 2019 | via check:Dec 25 15:38:00 2019 | FIGURE | TYPE | Oblong | Circle | SIZE | 47.0x20.0 | 59.0x24.0 | 63.0x28.0 | 63.0x35.0 | 70.0x24.0 | 71.0x22.0 | 75.0x28.0 | 98.0x59.0 | 10.0 | 12.0 | 14.0 | 22.0 | 32.0 | 110.0 | 118.0 | 126.0 | 134.0 | 150.0 | 154.0 | 33.0 | 40.0 | 41.0 | 43.0 | 47.0 | 63.0 | 67.0 | 71.0 | DRILL CHART: TOP to BOTTOM | ALL UNITS ARE IN MILS | PLATED | NON-PLATED | ROTATION | 0.000 | 90.000 | - | QTY | 2 | 6 | 4 | 1 | 30 | 5993 | 8 | 361 | 19 | 18 | 3 | 6427 | TOTAL HOLES: | GND | +3V | +VIN_CPU_GPU | +5V | PVADPTR | NVVDD | +VCCIN | +VCCPRIM_3P3 | +3VPCU | +1.8V_DEEP_SUS | +1.8VPCU | +5VPCU | TYPEC_VBUS | AGND
